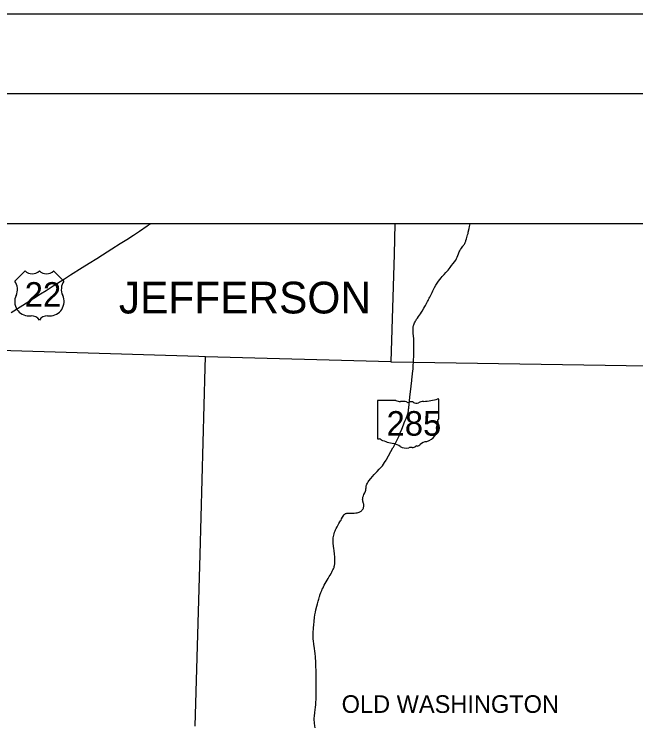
# Model space of a CAD drawing. Extents: x -29.6 to 34, y 0 to 22.
# Drawn here: x 10.805 to 14.718, y 17.521 to 22 of the extents above; entities that cross this region are included whole.
import ezdxf

# ---------------------------------------------------------------- set-up
doc = ezdxf.new("R2010")
doc.units = 0
for name, color, linetype in [('GM_X_Corporation_Text', 7, 'Continuous'), ('GM_X_State_Route', 7, 'Continuous'), ('GM_X_State_Shield', 7, 'Continuous'), ('GM_X_Township', 7, 'Continuous'), ('GM_X_Township_Text', 7, 'Continuous'), ('GM_X_US_Location', 7, 'Continuous'), ('GM_X_US_Route', 7, 'Continuous'), ('GM_X_US_Shield', 7, 'Continuous'), ('SH_Border', 7, 'Continuous'), ('SH_Cut_Line', 7, 'Continuous'), ('SH_Text', 7, 'Continuous')]:
    doc.layers.add(name, color=color, linetype=linetype)

msp = doc.modelspace()

# ---------------------------------------------------------------- linework, layer by layer
at = {"layer": 'GM_X_State_Route'}
for points in [[(13.3194, 19.8089), (13.3195, 19.8101), (13.3197, 19.8309), (13.3203, 19.8388), (13.3205, 19.8497), (13.3213, 19.8796), (13.3215, 19.8919), (13.3216, 19.9043), (13.3215, 19.9174), (13.3213, 19.929), (13.3205, 19.9464), (13.32, 19.9588), (13.3191, 19.9733), (13.3178, 19.9922), (13.3175, 19.9988), (13.3172, 20.006), (13.3171, 20.0111), (13.3169, 20.0177), (13.3171, 20.0258), (13.3174, 20.0309), (13.3189, 20.0397), (13.3201, 20.0447), (13.3222, 20.051), (13.3247, 20.0571), (13.3286, 20.0643), (13.3319, 20.0699), (13.3347, 20.0742), (13.3387, 20.0801), (13.3434, 20.087), (13.3509, 20.0977), (13.363, 20.1149), (13.369, 20.124), (13.3733, 20.1307), (13.3843, 20.1495), (13.3908, 20.1609), (13.3939, 20.1666), (13.4008, 20.1795), (13.4035, 20.1846), (13.4051, 20.1879), (13.4075, 20.1924), (13.4102, 20.1975), (13.4132, 20.2033), (13.4155, 20.2079), (13.4181, 20.213), (13.421, 20.2189), (13.4295, 20.2361), (13.4359, 20.2488), (13.4406, 20.258), (13.4455, 20.2679), (13.4519, 20.2801), (13.4599, 20.2949), (13.4677, 20.3074), (13.4762, 20.32), (13.4846, 20.3309), (13.4929, 20.3414), (13.4995, 20.3486), (13.5111, 20.361), (13.5232, 20.3746), (13.5362, 20.3897), (13.5498, 20.406), (13.5591, 20.4172), (13.5693, 20.4298), (13.5773, 20.4407), (13.5846, 20.452), (13.5904, 20.462), (13.5946, 20.4709), (13.5985, 20.4816), (13.6022, 20.4923), (13.6071, 20.5036), (13.611, 20.5112), (13.6151, 20.518), (13.6206, 20.5265), (13.6251, 20.5331), (13.6303, 20.5401), (13.6331, 20.5439), (13.6361, 20.5486), (13.639, 20.553), (13.6414, 20.5574), (13.6438, 20.5621), (13.6458, 20.5667), (13.6476, 20.5714), (13.649, 20.5756), (13.6525, 20.5867), (13.6573, 20.6027), (13.6597, 20.6111), (13.661, 20.6159), (13.6621, 20.6202), (13.664, 20.628), (13.6695, 20.6521), (13.6721, 20.6642), (13.6755, 20.6798)], [(12.7284, 18.3398), (12.7293, 18.3423), (12.7359, 18.3592), (12.741, 18.3721), (12.7448, 18.3808), (12.7492, 18.39), (12.7522, 18.3958), (12.7574, 18.4054), (12.7691, 18.4264), (12.7754, 18.4379), (12.7815, 18.4487), (12.7885, 18.4606), (12.7937, 18.4694), (12.802, 18.4839), (12.8042, 18.4877), (12.8077, 18.494), (12.8118, 18.5016), (12.8149, 18.5081), (12.8174, 18.514), (12.8187, 18.5181), (12.8201, 18.5229), (12.8214, 18.5299), (12.8227, 18.5393), (12.8235, 18.5523), (12.8239, 18.5639), (12.8237, 18.5762), (12.823, 18.5871), (12.822, 18.5986), (12.819, 18.6261), (12.8179, 18.6347), (12.8154, 18.6535), (12.814, 18.6673), (12.8131, 18.679), (12.813, 18.6863), (12.8132, 18.6958), (12.814, 18.7045), (12.8151, 18.7125), (12.8168, 18.7211), (12.8189, 18.7297), (12.8219, 18.7395), (12.8246, 18.7471), (12.8275, 18.7538), (12.8317, 18.7623), (12.8382, 18.7737), (12.8496, 18.7931), (12.8557, 18.8039), (12.8596, 18.8109), (12.8626, 18.8159), (12.8665, 18.8228), (12.872, 18.8331), (12.8763, 18.8407), (12.88, 18.8462), (12.8833, 18.8502), (12.8859, 18.8529), (12.8889, 18.8552), (12.8916, 18.8567), (12.8944, 18.8578), (12.8988, 18.8589), (12.904, 18.8595), (12.9113, 18.8598), (12.9222, 18.8599), (12.9295, 18.8599), (12.9381, 18.8599), (12.9461, 18.8602), (12.9554, 18.861), (12.9633, 18.8621), (12.9696, 18.8634), (12.9758, 18.8653), (12.981, 18.8675), (12.9847, 18.8696), (12.9888, 18.8724), (12.9926, 18.8757), (12.9959, 18.8794), (12.9989, 18.8834), (13.001, 18.887), (13.0031, 18.8916), (13.0046, 18.8963), (13.0057, 18.9011), (13.0061, 18.9061), (13.006, 18.9111), (13.0058, 18.9125), (13.0053, 18.916), (13.0042, 18.9208), (13.0002, 18.9341), (12.9996, 18.9372), (12.9989, 18.9419), (12.9987, 18.9464), (12.9993, 18.9523), (13.0005, 18.9592), (13.0031, 18.9675), (13.0069, 18.9759), (13.0122, 18.9865), (13.0149, 18.9923), (13.017, 18.9985), (13.0183, 19.0038), (13.0195, 19.0116), (13.0203, 19.0194), (13.0205, 19.0255), (13.0211, 19.0302), (13.0226, 19.0359), (13.0252, 19.0426), (13.0287, 19.049), (13.0328, 19.0556), (13.0384, 19.0633), (13.0505, 19.0779), (13.072, 19.1025), (13.0891, 19.1208), (13.1029, 19.1354), (13.1158, 19.1494), (13.1228, 19.1578), (13.1302, 19.1677), (13.1369, 19.1777), (13.1458, 19.1929), (13.1482, 19.197), (13.1622, 19.2205), (13.177, 19.2472), (13.1891, 19.2696), (13.1922, 19.2754), (13.1947, 19.2798), (13.2059, 19.3002), (13.2097, 19.3072), (13.2166, 19.3208), (13.2188, 19.3254), (13.2221, 19.3327), (13.228, 19.3459), (13.2355, 19.3654), (13.2444, 19.3883), (13.2557, 19.4155), (13.261, 19.4283), (13.2652, 19.4384), (13.2721, 19.4544), (13.2753, 19.4617), (13.2775, 19.467), (13.2799, 19.4729), (13.282, 19.479), (13.2836, 19.4852), (13.2848, 19.4909), (13.2857, 19.4965), (13.2866, 19.5022), (13.2874, 19.5087), (13.2881, 19.5144), (13.2886, 19.5194), (13.2888, 19.5209), (13.2891, 19.5237), (13.2896, 19.5287), (13.2907, 19.539), (13.2939, 19.5683), (13.2982, 19.6082), (13.3019, 19.6406), (13.3041, 19.6594), (13.3084, 19.6933), (13.3093, 19.7006), (13.3107, 19.7143), (13.3131, 19.7381), (13.3158, 19.7685), (13.3172, 19.7895), (13.3194, 19.8089)], [(12.7007, 17.5074), (12.6985, 17.5213), (12.6962, 17.5364), (12.6948, 17.5458), (12.694, 17.5539), (12.6938, 17.5612), (12.6941, 17.5692), (12.6951, 17.5808), (12.6978, 17.604), (12.7, 17.622), (12.7019, 17.6386), (12.7035, 17.6531), (12.7044, 17.6639), (12.7058, 17.6922), (12.7064, 17.7184), (12.7066, 17.7432), (12.7066, 17.7614), (12.7064, 17.7832), (12.706, 17.8086), (12.7058, 17.8217), (12.7057, 17.8436), (12.7057, 17.8472), (12.7054, 17.8676), (12.7048, 17.896), (12.7038, 17.92), (12.7015, 17.9548), (12.6996, 17.9751), (12.6979, 17.991), (12.6956, 18.0076), (12.6917, 18.0342), (12.6889, 18.0552), (12.6879, 18.0654), (12.6874, 18.0727), (12.6873, 18.08), (12.6874, 18.096), (12.6877, 18.1149), (12.6882, 18.1258), (12.6893, 18.1404), (12.6906, 18.1542), (12.6932, 18.1788), (12.6963, 18.2034), (12.6986, 18.2193), (12.7013, 18.2351), (12.7044, 18.2501), (12.7097, 18.2728), (12.7136, 18.2883), (12.7178, 18.3046), (12.7219, 18.3186), (12.7268, 18.3354), (12.7284, 18.3398)]]:
    msp.add_lwpolyline(points, dxfattribs=at)
at = {"layer": 'GM_X_State_Shield'}
for p, q in [((13.4779, 19.452), (13.4779, 19.5747)), ((13.0916, 19.5649), (13.0916, 19.3303)), ((13.2086, 19.5689), (13.0954, 19.5689)), ((13.4778, 19.4521), (13.4779, 19.452))]:
    msp.add_line(p, q, dxfattribs=at)
for centre, major_axis, start_param, end_param in [((13.3403, 19.8886), (0.4096, 0), 4.814394, 5.042369), ((13.4736, 19.5752), (0.0043, 0), 6.141152, 7.989035), ((13.0961, 19.5654), (0.00447, 0), 1.712693, 3.28349), ((13.2355, 19.5961), (0.0434, 0), 4.042523, 4.731795), ((13.2499, 19.4372), (0.1558, 0), 1.404758, 1.657858), ((13.2853, 19.5666), (0.0125, 0), 3.836095, 5.185415), ((13.3036, 19.5395), (0.026, 0), 0.950623, 2.079405), ((13.3372, 19.5766), (0.0313, 0), 4.081561, 5.145723), ((13.3925, 19.4973), (0.0824, 0), 1.699011, 2.107814), ((13.4769, 19.443), (0.00665, 0), 1.883978, 3.671073), ((13.4345, 19.4275), (0.0399, 0), 5.934695, 6.695948), ((13.4733, 19.4516), (0.0046, 0), 5.05454, 6.418171), ((13.3632, 19.3851), (0.1024, 0), 5.101752, 6.440018), ((13.4933, 19.4007), (0.0291, 0), 2.387724, 3.262537), ((13.0961, 19.3298), (0.00451, 0), 3.00124, 4.508301), ((13.0968, 19.3538), (0.0344, 0), 4.665946, 4.897461), ((13.1038, 19.3168), (0.0124, 0), 0.519207, 1.627899), ((13.2607, 19.5275), (0.2958, 0), 4.195997, 4.488961), ((13.4064, 19.2645), (0.0561, 0), 1.647645, 2.488434), ((13.1725, 19.225), (0.0925, 0), 0.823519, 1.323587), ((13.2726, 19.3156), (0.0587, 0), 4.026481, 4.996735), ((13.3065, 19.2346), (0.0483, 0), 1.495662, 1.94098), ((13.3108, 19.2981), (0.0313, 0), 4.691044, 5.507374), ((13.3391, 19.2754), (0.00881, 0), 1.147584, 2.315152), ((13.3353, 19.3076), (0.0331, 0), 4.937069, 5.64225)]:
    msp.add_ellipse(centre, major_axis=major_axis, ratio=0.8, start_param=start_param, end_param=end_param, dxfattribs=at)
at = {"layer": 'GM_X_Township'}
for points in [[(13.2018, 20.6798), (13.1972, 20.4897), (13.1757, 19.8128), (12.0094, 19.8432), (11.9667, 19.8448), (10.3631, 19.8945), (8.3857, 19.9434), (7.5502, 19.9616), (7.2204, 19.9686), (7.2242, 20.1907), (7.2354, 20.6798)], [(11.9448, 17.5176), (11.975, 18.5989), (12.0064, 19.7738), (12.0094, 19.8432)], [(13.1757, 19.8128), (13.3192, 19.8107), (15.0616, 19.7817), (16.0653, 19.7493), (16.4226, 19.7422), (17.6523, 19.71), (18.6156, 19.678), (18.9538, 19.6656)]]:
    msp.add_lwpolyline(points, dxfattribs=at)
at = {"layer": 'GM_X_US_Route'}
msp.add_lwpolyline([(10.7855, 20.1229), (10.8596, 20.1692), (10.9273, 20.2121), (10.9704, 20.2393), (11.0054, 20.2616), (11.049, 20.2893), (11.1218, 20.335), (11.1586, 20.3586), (11.2322, 20.4056), (11.2759, 20.4332), (11.3241, 20.4633), (11.3605, 20.4862), (11.4196, 20.5234), (11.4729, 20.5576), (11.513, 20.5827), (11.5559, 20.6102), (11.5944, 20.6351), (11.6429, 20.6674), (11.6487, 20.6712), (11.6619, 20.6798)], dxfattribs=at)
at = {"layer": 'GM_X_US_Shield'}
for p, q in [((10.8729, 20.3841), (10.8085, 20.3198)), ((11.1175, 20.3198), (11.0531, 20.3841)), ((10.8986, 20.1009), (10.9115, 20.1009)), ((11.0145, 20.1009), (11.0274, 20.1009))]:
    msp.add_line(p, q, dxfattribs=at)
for centre, radius, start, end in [((10.9179, 20.4301), 0.0644, 225.573, 314.427), ((11.0081, 20.4301), 0.0644, 225.573, 314.427), ((10.7347, 20.2681), 0.0901, 334.5471, 35.0009), ((11.1913, 20.2681), 0.0901, 144.9991, 205.4529), ((10.8976, 20.191), 0.0901, 154.8319, 270.6383), ((11.0284, 20.191), 0.0901, 269.3617, 25.1681), ((10.9115, 20.0365), 0.0644, 36.8699, 90), ((11.0145, 20.0365), 0.0644, 90, 143.1301)]:
    msp.add_arc(centre, radius, start, end, dxfattribs=at)
at = {"layer": 'SH_Border'}
msp.add_lwpolyline([(1.5, 21.5), (33.5, 21.5), (33.5, 0.5), (1.5, 0.5)], close=True, dxfattribs=at)
at = {"layer": 'SH_Cut_Line'}
msp.add_lwpolyline([(0, 0), (34, 0), (34, 22), (0, 22)], close=True, dxfattribs=at)
at = {"layer": 'SH_Text'}
msp.add_line((20.8747, 20.6798), (2.5893, 20.6798), dxfattribs=at)

# ---------------------------------------------------------------- texts
at = {"layer": 'GM_X_Corporation_Text'}
msp.add_text('OLD WASHINGTON', height=0.110973, rotation=0, dxfattribs=at).set_placement((12.8665, 17.602))
at = {"layer": 'GM_X_State_Shield'}
msp.add_text('285', height=0.1545, dxfattribs=at).set_placement((13.1492, 19.3469))
at = {"layer": 'GM_X_Township_Text'}
msp.add_text('JEFFERSON', height=0.19975, rotation=0, dxfattribs=at).set_placement((11.4635, 20.1164))
at = {"layer": 'GM_X_US_Location'}
for s in ['0', '/']:
    msp.add_text(s, height=0.000222, dxfattribs=at).set_placement((10.9629, 20.2349))
msp.add_text('22', height=0.000222, rotation=0, dxfattribs=at).set_placement((10.9171, 20.1889))
at = {"layer": 'GM_X_US_Shield'}
msp.add_text('22', height=0.1545, dxfattribs=at).set_placement((10.8707, 20.1588))

doc.saveas('drawing.dxf')
